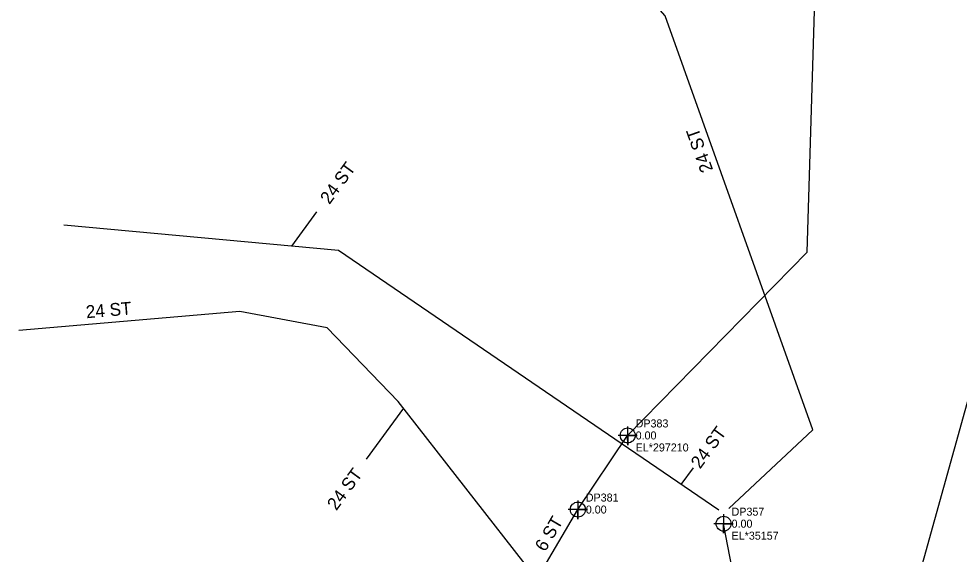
# Model space of a CAD drawing. Extents: x 1182504 to 1186036, y 573002 to 575111.
# Drawn here: x 1183573.3 to 1183867, y 573183.3 to 573350.5 of the extents above; entities that cross this region are included whole.
import ezdxf

# ---------------------------------------------------------------- set-up
doc = ezdxf.new("R2010")
doc.units = 0
for name, color, linetype in [('Exist Utilities Telephone UG Conduit SUE LOS B', 7, 'Continuous'), ('Exist Utilities Telephone UG Conduit SUE LOS B Cogo Comment', 7, 'Continuous'), ('Exist Utilities Telephone UG Conduit SUE LOS B Cogo Elevation', 7, 'Continuous'), ('Exist Utilities Telephone UG Conduit SUE LOS B Cogo Number', 7, 'Continuous'), ('Exist Utilities Telephone UG Conduit SUE LOS B Cogo Point CELL', 7, 'Continuous'), ('Exist Utilities Telephone UG Conduit SUE LOS B Leader', 7, 'Continuous'), ('Exist Utilities Telephone UG Conduit SUE LOS B Text', 7, 'Continuous'), ('Exist Utilities Telephone UG FO SUE LOS C', 7, 'Continuous'), ('Exist Utilities Telephone UG FO SUE LOS C Cogo Comment', 7, 'Continuous'), ('Exist Utilities Telephone UG FO SUE LOS C Cogo Elevation', 7, 'Continuous'), ('Exist Utilities Telephone UG FO SUE LOS C Cogo Number', 7, 'Continuous'), ('Exist Utilities Telephone UG FO SUE LOS C Cogo Point CELL', 7, 'Continuous'), ('Exist Utilities Telephone UG FO SUE LOS C Leader', 7, 'Continuous'), ('Exist Utilities Telephone UG FO SUE LOS C Text', 7, 'Continuous')]:
    doc.layers.add(name, color=color, linetype=linetype)

msp = doc.modelspace()

# ---------------------------------------------------------------- linework, layer by layer
at = {"layer": 'Exist Utilities Telephone UG Conduit SUE LOS B'}
msp.add_lwpolyline([(1183734.02, 573176.9), (1183691.83, 573230.97), (1183669.62, 573254.07), (1183642.4, 573259.08), (1183573.33, 573253.19)], dxfattribs=at)
at = {"layer": 'Exist Utilities Telephone UG Conduit SUE LOS B Cogo Point CELL'}
for points in [[(1183763.43, 573223.22), (1183763.47, 573217.41), (1183763.45, 573220.41), (1183766.47, 573220.41), (1183760.47, 573220.41)], [(1183747.87, 573200.07), (1183747.91, 573194.26), (1183747.89, 573197.26), (1183750.91, 573197.26), (1183744.91, 573197.26)]]:
    msp.add_lwpolyline(points, dxfattribs=at)
for centre in [(1183763.47, 573220.41), (1183747.91, 573197.26)]:
    msp.add_circle(centre, 2.34, dxfattribs=at)
at = {"layer": 'Exist Utilities Telephone UG Conduit SUE LOS B Leader'}
msp.add_line((1183693.41, 573228.94), (1183681.77, 573212.96), dxfattribs=at)
at = {"layer": 'Exist Utilities Telephone UG FO SUE LOS C'}
for points in [[(1183831.2, 573051.4), (1183831.99, 573067.67), (1183835.94, 573100.34), (1183843.81, 573135.41), (1183849.42, 573158.28), (1183872.21, 573240.17), (1183881.95, 573271.33), (1183882.59, 573295.88), (1183881.95, 573329.75), (1183881.17, 573370.19), (1183880.74, 573416.08), (1183881.11, 573461.73), (1183880.38, 573505.49), (1183880.23, 573552), (1183881.56, 573597.96), (1183880.77, 573642.04), (1183880.14, 573689.54)], [(1183763.45, 573220.41), (1183819.5, 573277.67), (1183831.72, 573678.52)], [(1183795.03, 573197.57), (1183821.29, 573222.16), (1183775.15, 573351.47), (1183690.62, 573447.81)], [(1183791.94, 573197.04), (1183673.12, 573278.22), (1183587.35, 573286.12)], [(1183736.02, 573177.04), (1183747.89, 573197.26), (1183763.45, 573220.41)], [(1183829.91, 573050.69), (1183824.94, 573066.76), (1183812.49, 573092.36), (1183807.57, 573119.77), (1183793.41, 573192.85)]]:
    msp.add_lwpolyline(points, dxfattribs=at)
at = {"layer": 'Exist Utilities Telephone UG FO SUE LOS C Cogo Point CELL'}
msp.add_lwpolyline([(1183793.41, 573195.85), (1183793.41, 573189.85), (1183793.41, 573192.85), (1183796.41, 573192.85), (1183790.41, 573192.85)], dxfattribs=at)
msp.add_circle((1183793.41, 573192.85), 2.34, dxfattribs=at)
at = {"layer": 'Exist Utilities Telephone UG FO SUE LOS C Leader'}
for p, q in [((1183658.59, 573279.56), (1183666.39, 573290.26)), ((1183780.19, 573205.07), (1183783.99, 573210.27))]:
    msp.add_line(p, q, dxfattribs=at)

# ---------------------------------------------------------------- texts
at = {"layer": 'Exist Utilities Telephone UG Conduit SUE LOS B Cogo Comment'}
msp.add_text('EL*297210', height=2.5, dxfattribs=at).set_placement((1183765.95, 573215.41))
at = {"layer": 'Exist Utilities Telephone UG Conduit SUE LOS B Cogo Elevation'}
for p in [(1183765.95, 573219.16), (1183750.39, 573196.01)]:
    msp.add_text('0.00', height=2.5, dxfattribs=at).set_placement(p)
at = {"layer": 'Exist Utilities Telephone UG Conduit SUE LOS B Cogo Number'}
for s, p in [('DP383', (1183765.95, 573222.91)), ('DP381', (1183750.39, 573199.76))]:
    msp.add_text(s, height=2.5, dxfattribs=at).set_placement(p)
at = {"layer": 'Exist Utilities Telephone UG Conduit SUE LOS B Text'}
for rotation, p in [(4.8737, (1183594.44, 573257)), (53.9157, (1183672.49, 573196.72))]:
    msp.add_text('24 ST', height=4, rotation=rotation, dxfattribs=at).set_placement(p)
at = {"layer": 'Exist Utilities Telephone UG FO SUE LOS C Cogo Comment'}
msp.add_text('EL*35157', height=2.5, dxfattribs=at).set_placement((1183795.91, 573187.85))
at = {"layer": 'Exist Utilities Telephone UG FO SUE LOS C Cogo Elevation'}
msp.add_text('0.00', height=2.5, dxfattribs=at).set_placement((1183795.91, 573191.6))
at = {"layer": 'Exist Utilities Telephone UG FO SUE LOS C Cogo Number'}
msp.add_text('DP357', height=2.5, dxfattribs=at).set_placement((1183795.91, 573195.35))
at = {"layer": 'Exist Utilities Telephone UG FO SUE LOS C Text'}
for s, rotation, p in [('24 ST', 109.6358, (1183790.19, 573303.38)), ('24 ST', 53.9157, (1183670.33, 573292.34)), ('24 ST', 53.9157, (1183786.08, 573209.76)), ('6 ST', 59.5764, (1183737.7, 573183.85))]:
    msp.add_text(s, height=4, rotation=rotation, dxfattribs=at).set_placement(p)

doc.saveas('drawing.dxf')
